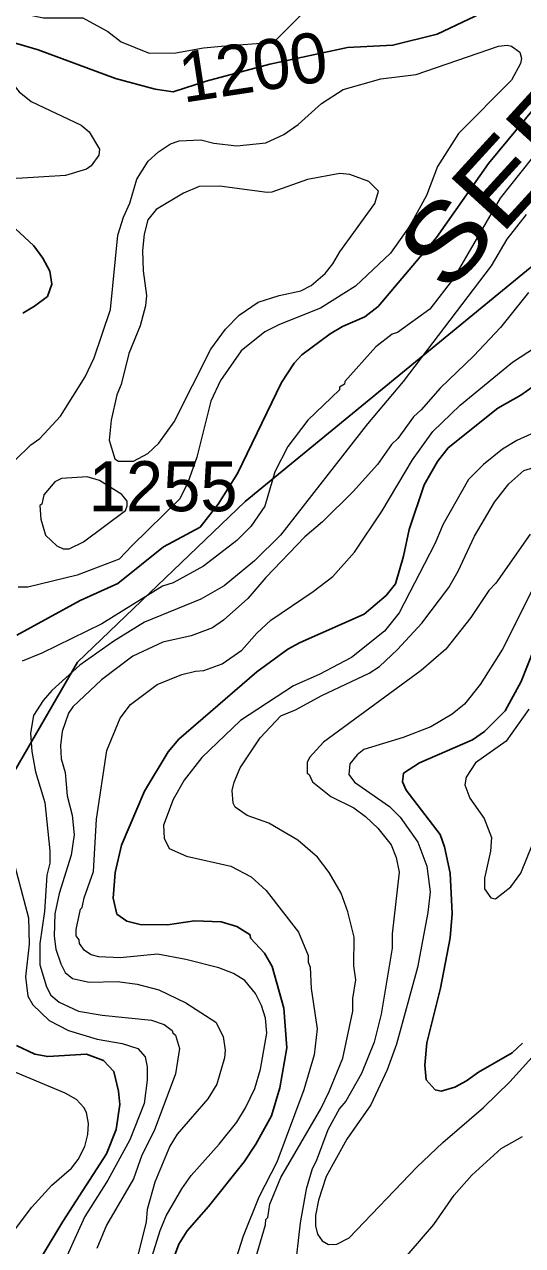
# Model space of a CAD drawing. Extents: x 598.3 to 623.2, y 6902.2 to 6930.1.
# Drawn here: x 612.063 to 612.859, y 6922.807 to 6924.757 of the extents above; entities that cross this region are included whole.
import ezdxf
from ezdxf.enums import TextEntityAlignment as Align

# ---------------------------------------------------------------- set-up
doc = ezdxf.new("R2010")
doc.units = 0
doc.header["$LTSCALE"] = 0.032
for name, color, linetype, lineweight in [('1', 7, 'Continuous', 25), ('2', 7, 'Continuous', 13), ('26', 7, 'Continuous', 25)]:
    doc.layers.add(name, color=color, linetype=linetype, lineweight=lineweight)
doc.layers.add('21', color=7, linetype='Continuous')
doc.layers.add('61', color=7, linetype='Continuous')

msp = doc.modelspace()

# ---------------------------------------------------------------- linework, layer by layer
at = {"layer": '1'}
for points in [[(612.3532, 6924.6666), (612.4552, 6924.6937), (612.5792, 6924.7202), (612.6518, 6924.7241), (612.7228, 6924.7415), (612.8227, 6924.7892)], [(613.0305, 6924.7582), (612.956, 6924.6983), (612.879, 6924.6252), (612.8048, 6924.535), (612.7214, 6924.417), (612.6284, 6924.3068), (612.6069, 6924.2902), (612.5715, 6924.2749), (612.5515, 6924.2632), (612.5065, 6924.2294), (612.4938, 6924.2164), (612.4736, 6924.1851), (612.4033, 6924.0397), (612.3728, 6923.991), (612.344, 6923.9544), (612.2851, 6923.9228), (612.2123, 6923.8642), (612.152, 6923.8369), (612.0509, 6923.7815)], [(612.0026, 6924.7405), (612.0849, 6924.7167), (612.2086, 6924.6708), (612.2717, 6924.6538), (612.3006, 6924.6498), (612.3532, 6924.6666)], [(612.0602, 6924.2962), (612.0793, 6924.3073), (612.0996, 6924.3229), (612.1069, 6924.3421), (612.1036, 6924.3633), (612.0925, 6924.384), (612.0779, 6924.4034), (612.0335, 6924.4447)], [(612.414, 6922.9402), (612.4328, 6922.9684), (612.4579, 6923.0139), (612.4712, 6923.0586), (612.4825, 6923.1227), (612.4777, 6923.1859), (612.459, 6923.2525), (612.4468, 6923.2736), (612.4245, 6923.2977), (612.4239, 6923.3029), (612.4023, 6923.3165), (612.3772, 6923.3238), (612.3345, 6923.3254), (612.2917, 6923.319), (612.248, 6923.3197), (612.2265, 6923.3248), (612.2106, 6923.336), (612.2049, 6923.3618), (612.208, 6923.4028), (612.218, 6923.446), (612.2549, 6923.5324), (612.2927, 6923.5951), (612.3098, 6923.6158), (612.4345, 6923.7233), (612.4839, 6923.7592), (612.5038, 6923.77), (612.606, 6923.815), (612.6409, 6923.8449), (612.656, 6923.8637), (612.6686, 6923.9079), (612.6776, 6923.9506), (612.702, 6924.022), (612.7231, 6924.0591), (612.7403, 6924.0809), (612.8196, 6924.1442), (612.8564, 6924.1648), (612.9105, 6924.2034)], [(612.8972, 6923.8098), (612.8567, 6923.7078), (612.8315, 6923.6607), (612.7981, 6923.6279), (612.7791, 6923.6146), (612.6946, 6923.578), (612.6689, 6923.5611), (612.6671, 6923.5475), (612.6729, 6923.534), (612.7276, 6923.4631), (612.7343, 6923.4433), (612.7431, 6923.4015), (612.7463, 6923.337), (612.7432, 6923.2982), (612.7279, 6923.2176), (612.7063, 6923.1303), (612.7027, 6923.0948), (612.7052, 6923.0715), (612.7195, 6923.0553), (612.7291, 6923.0535), (612.7507, 6923.0597), (612.7696, 6923.0695), (612.7888, 6923.0835), (612.8425, 6923.1146), (612.8591, 6923.13)], [(612.0503, 6923.1263), (612.0797, 6923.1125), (612.1001, 6923.1085), (612.1619, 6923.1125), (612.1894, 6923.102), (612.2057, 6923.0847), (612.2135, 6923.0532), (612.2153, 6923.0321), (612.2098, 6922.9922), (612.1943, 6922.953), (612.1244, 6922.8453), (612.0914, 6922.7901)], [(612.2929, 6922.7629), (612.3099, 6922.8087), (612.3232, 6922.8303), (612.3573, 6922.869), (612.414, 6922.9402)]]:
    msp.add_lwpolyline(points, dxfattribs=at)
at = {"layer": '2'}
for points in [[(612.0464, 6924.7774), (612.0934, 6924.768), (612.1565, 6924.768), (612.1961, 6924.7461), (612.2173, 6924.7297), (612.2621, 6924.7113), (612.3047, 6924.7121), (612.3491, 6924.7201), (612.3777, 6924.7225), (612.4613, 6924.7291), (612.5025, 6924.7701), (612.5306, 6924.8039), (612.5587, 6924.831)], [(613.1536, 6924.7894), (613.0901, 6924.7552), (613.0005, 6924.6813), (612.908, 6924.5864), (612.8231, 6924.4795), (612.7488, 6924.3515), (612.7109, 6924.3026), (612.6591, 6924.2654), (612.6505, 6924.2624), (612.6245, 6924.2421), (612.5749, 6924.1867), (612.5744, 6924.1824), (612.5667, 6924.1776), (612.5664, 6924.1736), (612.5159, 6924.1252), (612.484, 6924.0829), (612.4632, 6924.0426), (612.4469, 6923.9879), (612.425, 6923.9553), (612.4025, 6923.9327), (612.3491, 6923.8919), (612.3009, 6923.8654), (612.2838, 6923.8598), (612.1868, 6923.8)], [(612.837, 6924.0232), (612.8613, 6924.0448), (612.8716, 6924.0477), (612.9186, 6924.0757), (612.9814, 6924.0985), (613.0122, 6924.105), (613.0575, 6924.1229), (613.0792, 6924.1372), (613.1029, 6924.1587), (613.152, 6924.2237), (613.1774, 6924.2617), (613.2079, 6924.3002), (613.227, 6924.32), (613.3187, 6924.394), (613.35, 6924.4253), (613.3866, 6924.4846), (613.427, 6924.5313), (613.471, 6924.5904), (613.5226, 6924.673), (613.5555, 6924.7076), (613.6026, 6924.7386), (613.642, 6924.7587)], [(612.0227, 6924.0369), (612.0733, 6924.0859), (612.0878, 6924.0956), (612.1207, 6924.1315), (612.1602, 6924.1946), (612.1743, 6924.2245), (612.2007, 6924.3017), (612.2123, 6924.4204), (612.2215, 6924.4496), (612.2315, 6924.4716), (612.2427, 6924.5103), (612.2608, 6924.539), (612.277, 6924.5536), (612.2963, 6924.5663), (612.3103, 6924.5713), (612.3449, 6924.5728), (612.3658, 6924.5676), (612.4022, 6924.5632), (612.4488, 6924.568), (612.4774, 6924.5816), (612.5002, 6924.5973), (612.5376, 6924.6311), (612.5726, 6924.6535), (612.6325, 6924.6706), (612.6891, 6924.6774), (612.8206, 6924.7225), (612.8344, 6924.7243), (612.8412, 6924.7224), (612.8548, 6924.7127), (612.8571, 6924.7029), (612.8556, 6924.6951), (612.8415, 6924.6684), (612.7568, 6924.5831), (612.7232, 6924.5305), (612.7057, 6924.4841), (612.6791, 6924.4358), (612.6478, 6924.3918), (612.5921, 6924.3394), (612.5362, 6924.3042), (612.4706, 6924.2779), (612.4474, 6924.2663), (612.4093, 6924.2357), (612.3761, 6924.1886), (612.3606, 6924.1552), (612.3387, 6924.0662), (612.3242, 6924.0257), (612.3112, 6923.9993), (612.2351, 6923.9248), (612.2142, 6923.9032), (612.1474, 6923.8774), (612.0686, 6923.8581), (612.0529, 6923.8584)], [(612.865, 6924.4538), (612.8338, 6924.4141), (612.8089, 6924.3716), (612.668, 6924.187), (612.6112, 6924.1195), (612.4721, 6923.9416), (612.4308, 6923.9003), (612.3819, 6923.8603), (612.3447, 6923.8393), (612.2548, 6923.8025), (612.2056, 6923.7722), (612.1517, 6923.7338), (612.1067, 6923.6934), (612.0931, 6923.6775), (612.0775, 6923.6535), (612.0729, 6923.6252), (612.0746, 6923.5959), (612.0809, 6923.5634), (612.0956, 6923.5146), (612.1036, 6923.4374), (612.1036, 6923.4177), (612.0988, 6923.3985), (612.0948, 6923.3403), (612.0874, 6923.2889), (612.0875, 6923.2551), (612.0981, 6923.22), (612.1053, 6923.2066), (612.1183, 6923.1953), (612.1496, 6923.1812), (612.1873, 6923.1749), (612.2658, 6923.1667), (612.2861, 6923.1597), (612.2993, 6923.1499), (612.2999, 6923.1462), (612.3045, 6923.1429), (612.3108, 6923.1214), (612.3044, 6923.0809), (612.2702, 6922.9898), (612.2507, 6922.9509), (612.2375, 6922.9132), (612.1941, 6922.8391), (612.1788, 6922.802)], [(612.8686, 6924.3291), (612.824, 6924.2734), (612.7812, 6924.2281), (612.7273, 6924.1764), (612.6972, 6924.1416), (612.6847, 6924.1306), (612.6595, 6924.0958), (612.6494, 6924.0865), (612.627, 6924.0542), (612.5881, 6924.0113), (612.5393, 6923.9626), (612.5112, 6923.9385), (612.449, 6923.8739), (612.42, 6923.8401), (612.3813, 6923.8055), (612.3633, 6923.7936), (612.3293, 6923.7808), (612.2844, 6923.7704), (612.2363, 6923.748), (612.186, 6923.7105), (612.1402, 6923.6672), (612.1334, 6923.6571), (612.123, 6923.6278), (612.1206, 6923.6055), (612.1215, 6923.5842), (612.1278, 6923.5624), (612.1314, 6923.5252), (612.1391, 6923.4944), (612.1425, 6923.4625), (612.1375, 6923.4301), (612.1182, 6923.3691), (612.1117, 6923.3364), (612.1103, 6923.301), (612.1134, 6923.2799), (612.1209, 6923.2569), (612.1281, 6923.2429), (612.1396, 6923.2332), (612.1666, 6923.2275), (612.2116, 6923.2282), (612.2432, 6923.2242), (612.2775, 6923.2151), (612.3209, 6923.1941), (612.369, 6923.1635), (612.3804, 6923.1408), (612.3837, 6923.1185), (612.3828, 6923.1063), (612.3707, 6923.0647), (612.3563, 6923.0412), (612.3073, 6922.9846), (612.2951, 6922.9653), (612.2715, 6922.9077), (612.2591, 6922.8643)], [(612.415, 6923.2303), (612.397, 6923.2411), (612.3735, 6923.2503), (612.3209, 6923.2638), (612.2755, 6923.2719), (612.2159, 6923.2664), (612.1816, 6923.2679), (612.1698, 6923.2713), (612.1591, 6923.2779), (612.1507, 6923.2889), (612.1505, 6923.2952), (612.1458, 6923.3014), (612.1458, 6923.3114), (612.1523, 6923.3438), (612.1554, 6923.3467), (612.1582, 6923.362), (612.1731, 6923.4042), (612.1782, 6923.4876), (612.1944, 6923.5974), (612.216, 6923.649), (612.2323, 6923.6709), (612.2752, 6923.7026), (612.3147, 6923.719), (612.3366, 6923.7244), (612.3498, 6923.725), (612.3792, 6923.7357), (612.4106, 6923.7578), (612.4345, 6923.785), (612.4569, 6923.8058), (612.5244, 6923.8514), (612.5557, 6923.8753), (612.5904, 6923.9141), (612.6348, 6923.9801), (612.6829, 6924.0615), (612.7158, 6924.1068), (612.7591, 6924.1493), (612.8432, 6924.2178), (612.88, 6924.2416)], [(612.8948, 6924.1127), (612.8498, 6924.0927), (612.8268, 6924.0786), (612.7964, 6924.0545), (612.7727, 6924.0301), (612.7321, 6923.959), (612.7187, 6923.9275), (612.6618, 6923.8171), (612.6383, 6923.788), (612.5859, 6923.7462), (612.5342, 6923.7187), (612.4928, 6923.7005), (612.4082, 6923.6456), (612.3465, 6923.586), (612.318, 6923.5502), (612.3009, 6923.5192), (612.285, 6923.4779), (612.2863, 6923.4575), (612.2941, 6923.441), (612.3221, 6923.4286), (612.3928, 6923.4125), (612.4253, 6923.3954), (612.4494, 6923.3738), (612.501, 6923.3075), (612.5164, 6923.27), (612.5165, 6923.2593), (612.5197, 6923.2515), (612.5213, 6923.2172), (612.531, 6923.1527), (612.5261, 6923.1111), (612.5097, 6923.0556), (612.4662, 6922.9399), (612.4374, 6922.884), (612.4127, 6922.8217), (612.3804, 6922.7215)], [(612.4321, 6922.7854), (612.4484, 6922.8397), (612.4485, 6922.8483), (612.4517, 6922.8514), (612.4554, 6922.8727), (612.4725, 6922.9153), (612.5364, 6923.0252), (612.5502, 6923.0529), (612.5717, 6923.1058), (612.5877, 6923.1813), (612.5878, 6923.2013), (612.5925, 6923.2309), (612.5894, 6923.2536), (612.5901, 6923.2995), (612.5797, 6923.3398), (612.569, 6923.3694), (612.55, 6923.4026), (612.5312, 6923.4272), (612.4997, 6923.4542), (612.4536, 6923.4815), (612.4188, 6923.4936), (612.3997, 6923.5069), (612.3966, 6923.5135), (612.3951, 6923.5334), (612.3983, 6923.547), (612.4079, 6923.5697), (612.4397, 6923.6176), (612.4726, 6923.653), (612.496, 6923.6624), (612.5385, 6923.6853), (612.614, 6923.7208), (612.6306, 6923.7318), (612.6593, 6923.7589), (612.6982, 6923.801), (612.7411, 6923.8578), (612.7559, 6923.8837), (612.7823, 6923.9396), (612.8143, 6923.994), (612.837, 6924.0232)], [(612.871, 6923.9432), (612.8161, 6923.8648), (612.805, 6923.8531), (612.7765, 6923.8098), (612.7364, 6923.7591), (612.6971, 6923.7251), (612.5411, 6923.6105), (612.5185, 6923.586), (612.5149, 6923.5784), (612.5149, 6923.5613), (612.518, 6923.5593), (612.5236, 6923.5474), (612.5529, 6923.5237), (612.5893, 6923.5059), (612.608, 6923.492), (612.6277, 6923.4732), (612.6491, 6923.4468), (612.6572, 6923.4263), (612.6621, 6923.4031), (612.6509, 6923.3046), (612.6508, 6923.2818), (612.633, 6923.1762), (612.6219, 6923.1317), (612.6017, 6923.0815), (612.5765, 6923.0375), (612.5663, 6923.0254), (612.5479, 6922.9917), (612.5294, 6922.9417), (612.5226, 6922.9294)], [(612.8766, 6923.8578), (612.8272, 6923.7591), (612.7914, 6923.7027), (612.7662, 6923.6714), (612.7467, 6923.6553), (612.7122, 6923.6353), (612.6685, 6923.6183), (612.6053, 6923.5988), (612.5949, 6923.5907), (612.583, 6923.5763), (612.5814, 6923.5592), (612.5905, 6923.5469), (612.6465, 6923.5079), (612.6637, 6923.4912), (612.6917, 6923.4509), (612.7059, 6923.4125), (612.7115, 6923.3718), (612.7076, 6923.3386), (612.6913, 6923.251), (612.6574, 6923.1282), (612.6426, 6923.0872), (612.6167, 6923.0313), (612.5783, 6922.9765), (612.5454, 6922.9169), (612.5327, 6922.8789), (612.5279, 6922.8546), (612.5279, 6922.838), (612.5311, 6922.8246), (612.5389, 6922.8143), (612.5487, 6922.8083), (612.5623, 6922.8089), (612.5819, 6922.8192), (612.6902, 6922.9317), (612.7317, 6922.9714), (612.7967, 6923.0269), (612.8388, 6923.0681)], [(612.1868, 6923.8), (612.091, 6923.7529), (612.0593, 6923.7404)], [(612.8693, 6923.6636), (612.8331, 6923.6123), (612.7841, 6923.5775), (612.769, 6923.5551), (612.7666, 6923.5424), (612.7749, 6923.5213), (612.7975, 6923.4887), (612.8094, 6923.4585), (612.8078, 6923.4366), (612.7982, 6923.3937), (612.7982, 6923.3767), (612.8086, 6923.3621), (612.8159, 6923.3604), (612.8401, 6923.3794), (612.8563, 6923.4013), (612.8949, 6923.4964)], [(612.0403, 6923.4409), (612.0696, 6923.3303), (612.0704, 6923.288), (612.0648, 6923.2357), (612.0683, 6923.2051), (612.0764, 6923.1911), (612.1026, 6923.1664), (612.1335, 6923.1501), (612.1792, 6923.1361), (612.2189, 6923.1295), (612.2444, 6923.1214), (612.2558, 6923.1082), (612.259, 6923.0923), (612.259, 6923.071), (612.2544, 6923.0338), (612.2314, 6922.9756), (612.1961, 6922.9112), (612.1594, 6922.8528), (612.1173, 6922.7605)], [(612.2671, 6922.7895), (612.2798, 6922.8306), (612.2897, 6922.8541), (612.3146, 6922.8975), (612.3293, 6922.9183), (612.3744, 6922.9687), (612.4024, 6923.0039), (612.4164, 6923.0265), (612.431, 6923.0576), (612.4402, 6923.0884), (612.4501, 6923.146), (612.448, 6923.1701), (612.4418, 6923.19), (612.4322, 6923.2091), (612.415, 6923.2303)], [(612.8388, 6923.0681), (612.879, 6923.1131)], [(612.0193, 6922.7828), (612.0438, 6922.8268), (612.0749, 6922.8677), (612.107, 6922.903), (612.138, 6922.93), (612.1489, 6922.9439), (612.1597, 6922.965), (612.1643, 6922.9838), (612.1651, 6923.0016), (612.1619, 6923.0194), (612.1578, 6923.0274), (612.1461, 6923.0402), (612.1282, 6923.05), (612.0494, 6923.0833)], [(612.6579, 6922.7715), (612.717, 6922.8403), (612.7498, 6922.8869), (612.7779, 6922.9189), (612.8247, 6922.9618), (612.8592, 6922.981)], [(612.5226, 6922.9294), (612.5133, 6922.8967), (612.5035, 6922.8427), (612.4978, 6922.7911)], [(612.2591, 6922.8643), (612.2574, 6922.8444), (612.2446, 6922.7931)]]:
    msp.add_lwpolyline(points, dxfattribs=at)
for points in [[(612.0275, 6924.5156), (611.9996, 6924.5335), (611.9759, 6924.5532), (611.9566, 6924.5926), (611.9522, 6924.6093), (611.9498, 6924.6368), (611.9467, 6924.6455), (611.9481, 6924.6639), (611.9664, 6924.6986), (611.9802, 6924.7072), (611.9909, 6924.7071), (612.0089, 6924.7001), (612.0237, 6924.6875), (612.0543, 6924.6497), (612.0737, 6924.6343), (612.1538, 6924.5963), (612.1666, 6924.5859), (612.1828, 6924.5581), (612.1818, 6924.5486), (612.1696, 6924.5312), (612.1623, 6924.5258), (612.1286, 6924.516), (612.0509, 6924.5114)], [(612.5672, 6924.3939), (612.6232, 6924.4714), (612.629, 6924.4909), (612.6135, 6924.5064), (612.5829, 6924.5177), (612.5668, 6924.5194), (612.5152, 6924.5097), (612.4585, 6924.4895), (612.451, 6924.4887), (612.3746, 6924.4991), (612.3422, 6924.4984), (612.3171, 6924.4877), (612.2733, 6924.4615), (612.2604, 6924.4452), (612.2543, 6924.422), (612.2518, 6924.3963), (612.2526, 6924.3639), (612.2582, 6924.3243), (612.2566, 6924.3079), (612.2478, 6924.276), (612.2298, 6924.2315), (612.2177, 6924.1819), (612.2105, 6924.1654), (612.2016, 6924.125), (612.1984, 6924.0929), (612.2072, 6924.0631), (612.2132, 6924.0596), (612.2373, 6924.0595), (612.2602, 6924.0717), (612.2775, 6924.0885), (612.3022, 6924.1224), (612.361, 6924.2385), (612.3841, 6924.2705), (612.4061, 6924.2931), (612.4366, 6924.3136), (612.4698, 6924.3244), (612.5046, 6924.3315), (612.5213, 6924.34), (612.5436, 6924.3596), (612.5561, 6924.3746)], [(612.2245, 6923.9807), (612.2272, 6923.9881), (612.2269, 6923.9958), (612.2184, 6924.0065), (612.1828, 6924.0289), (612.163, 6924.0346), (612.122, 6924.0321), (612.1117, 6924.0264), (612.094, 6924.006), (612.0906, 6923.991), (612.0875, 6923.9889), (612.0893, 6923.9671), (612.0968, 6923.9412), (612.1147, 6923.9246), (612.1248, 6923.9196), (612.1345, 6923.9197), (612.1576, 6923.9309)]]:
    msp.add_lwpolyline(points, close=True, dxfattribs=at)
at = {"layer": '26'}
msp.add_lwpolyline([(611.7954, 6922.5408), (611.9289, 6923.1752), (612.0273, 6923.5305), (612.1476, 6923.7383), (612.4155, 6923.9952), (613.383, 6924.7878), (613.5033, 6924.9409), (613.7001, 6925.1814), (614.4217, 6926.395), (614.5438, 6926.7862), (614.6262, 6927.0228), (614.6475, 6927.193), (614.6688, 6927.3792), (614.6688, 6927.5892), (614.6788, 6927.929)], dxfattribs=at)

# ---------------------------------------------------------------- texts
at = {"layer": '21'}
msp.add_text('1255', height=0.08, dxfattribs=at).set_placement((612.1656, 6923.9796))
at = {"layer": '26', "width": 1.2}
msp.add_text('SERRA DA BOCAINA', height=0.12, rotation=47.594, dxfattribs=at).set_placement((613.3793, 6925.027), align=Align.CENTER)
at = {"layer": '61'}
msp.add_text('1200', height=0.08, rotation=8.673, dxfattribs=at).set_placement((612.4344, 6924.65), align=Align.CENTER)

doc.saveas('drawing.dxf')
